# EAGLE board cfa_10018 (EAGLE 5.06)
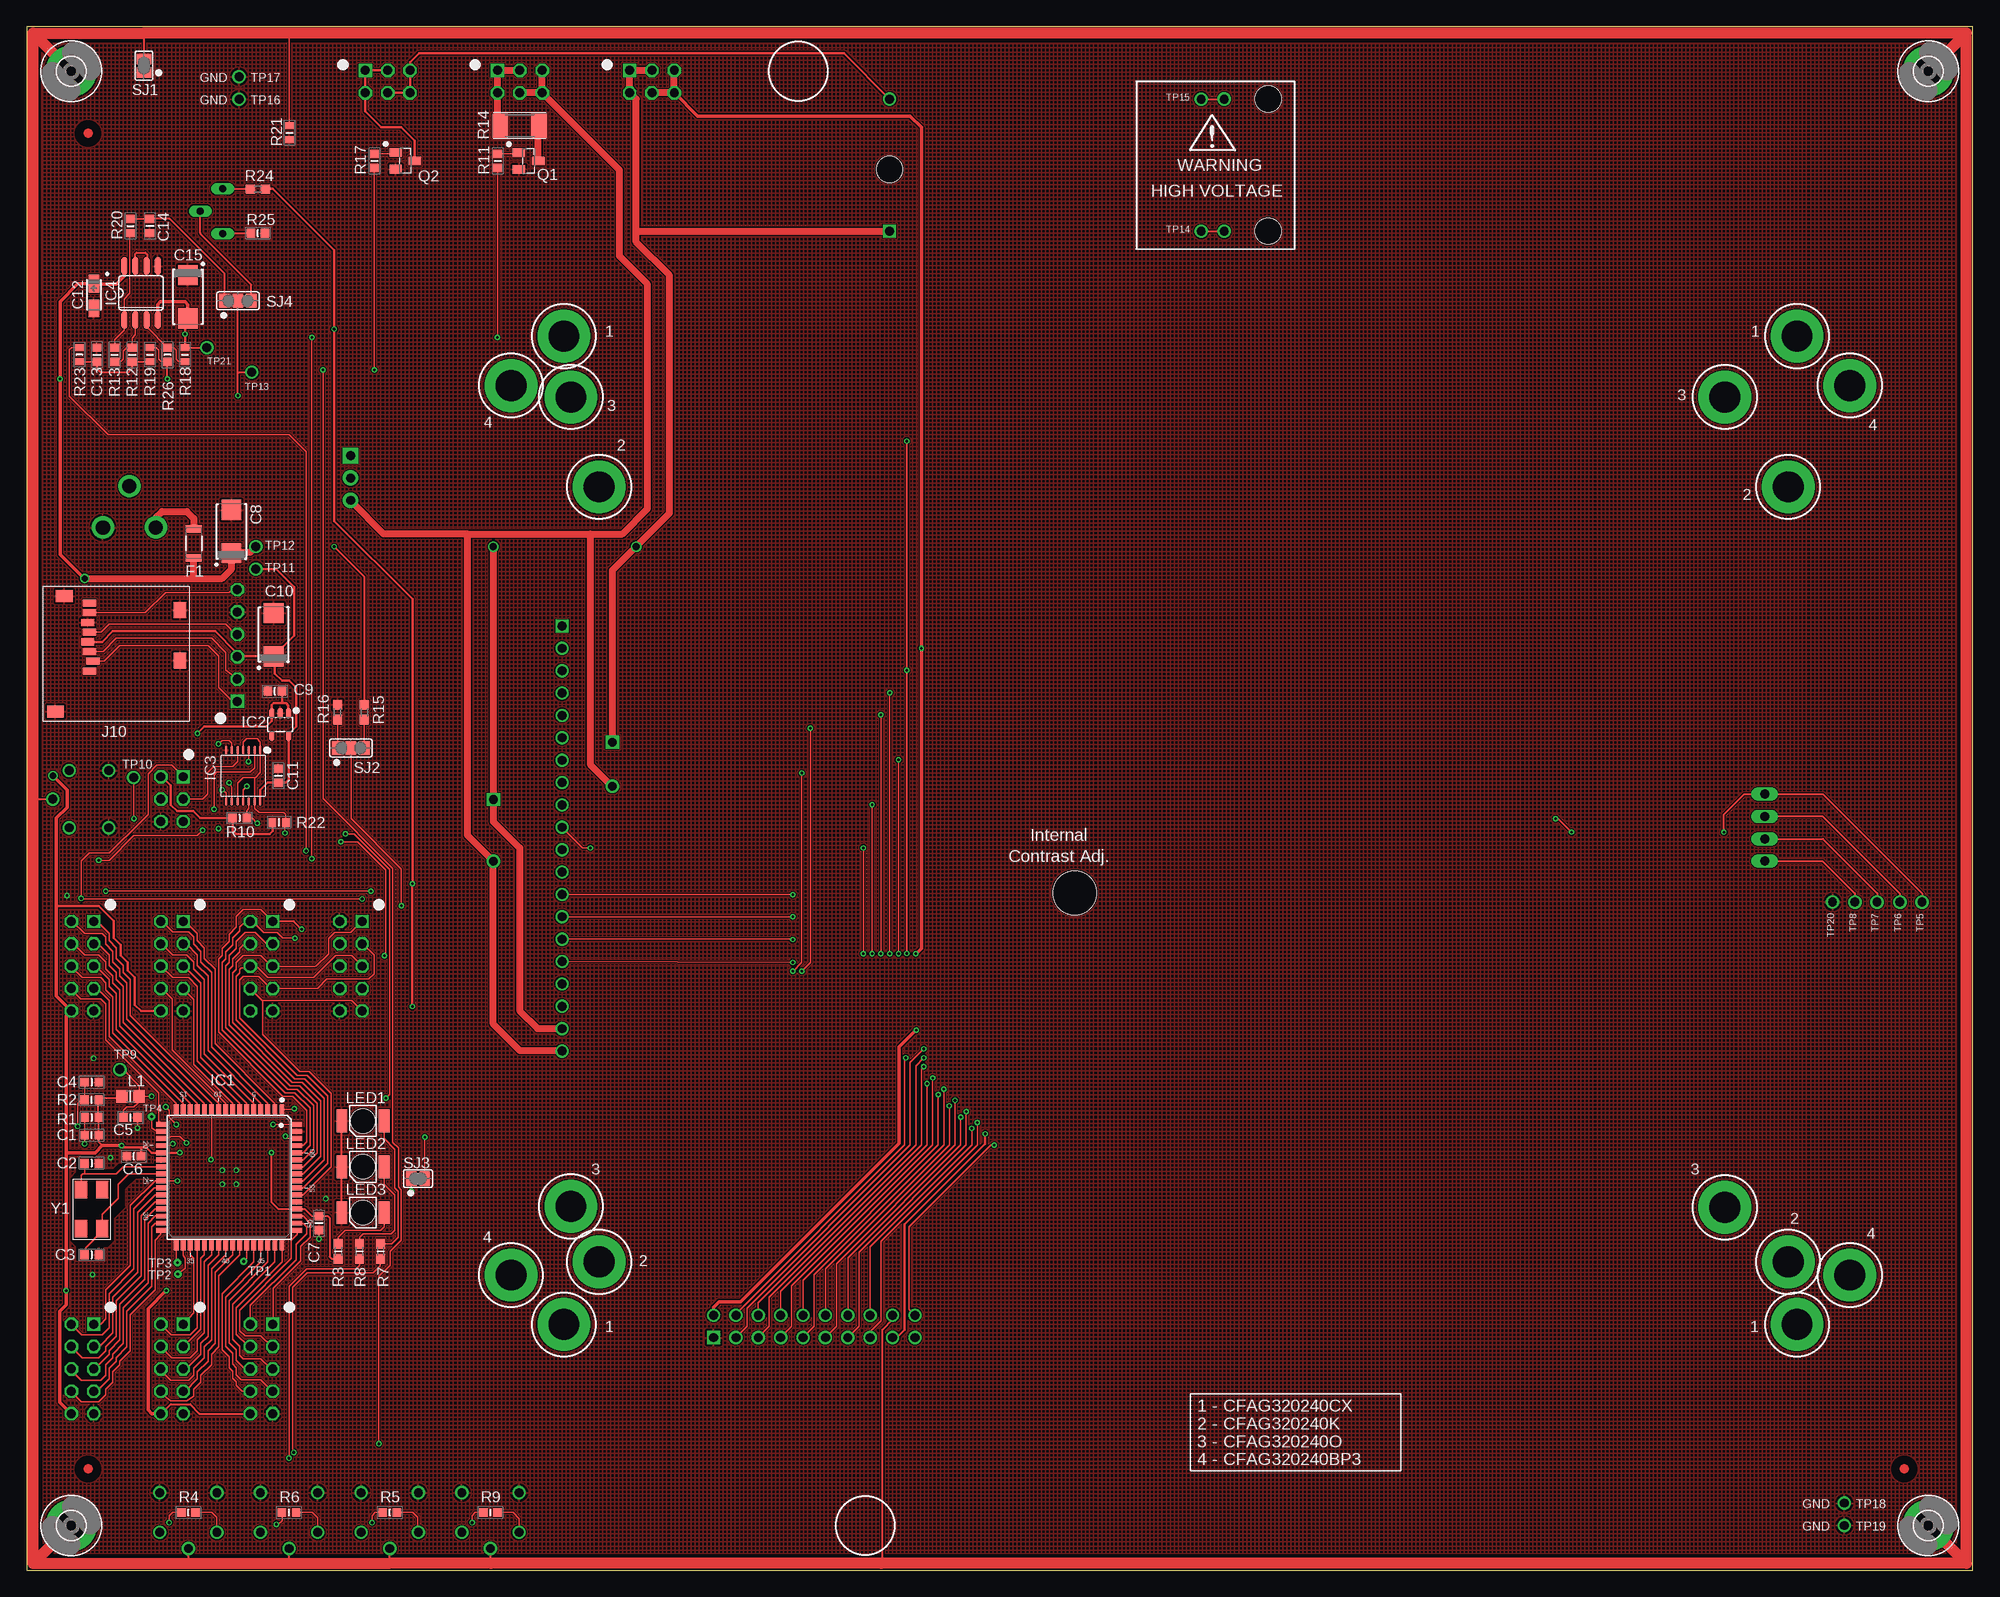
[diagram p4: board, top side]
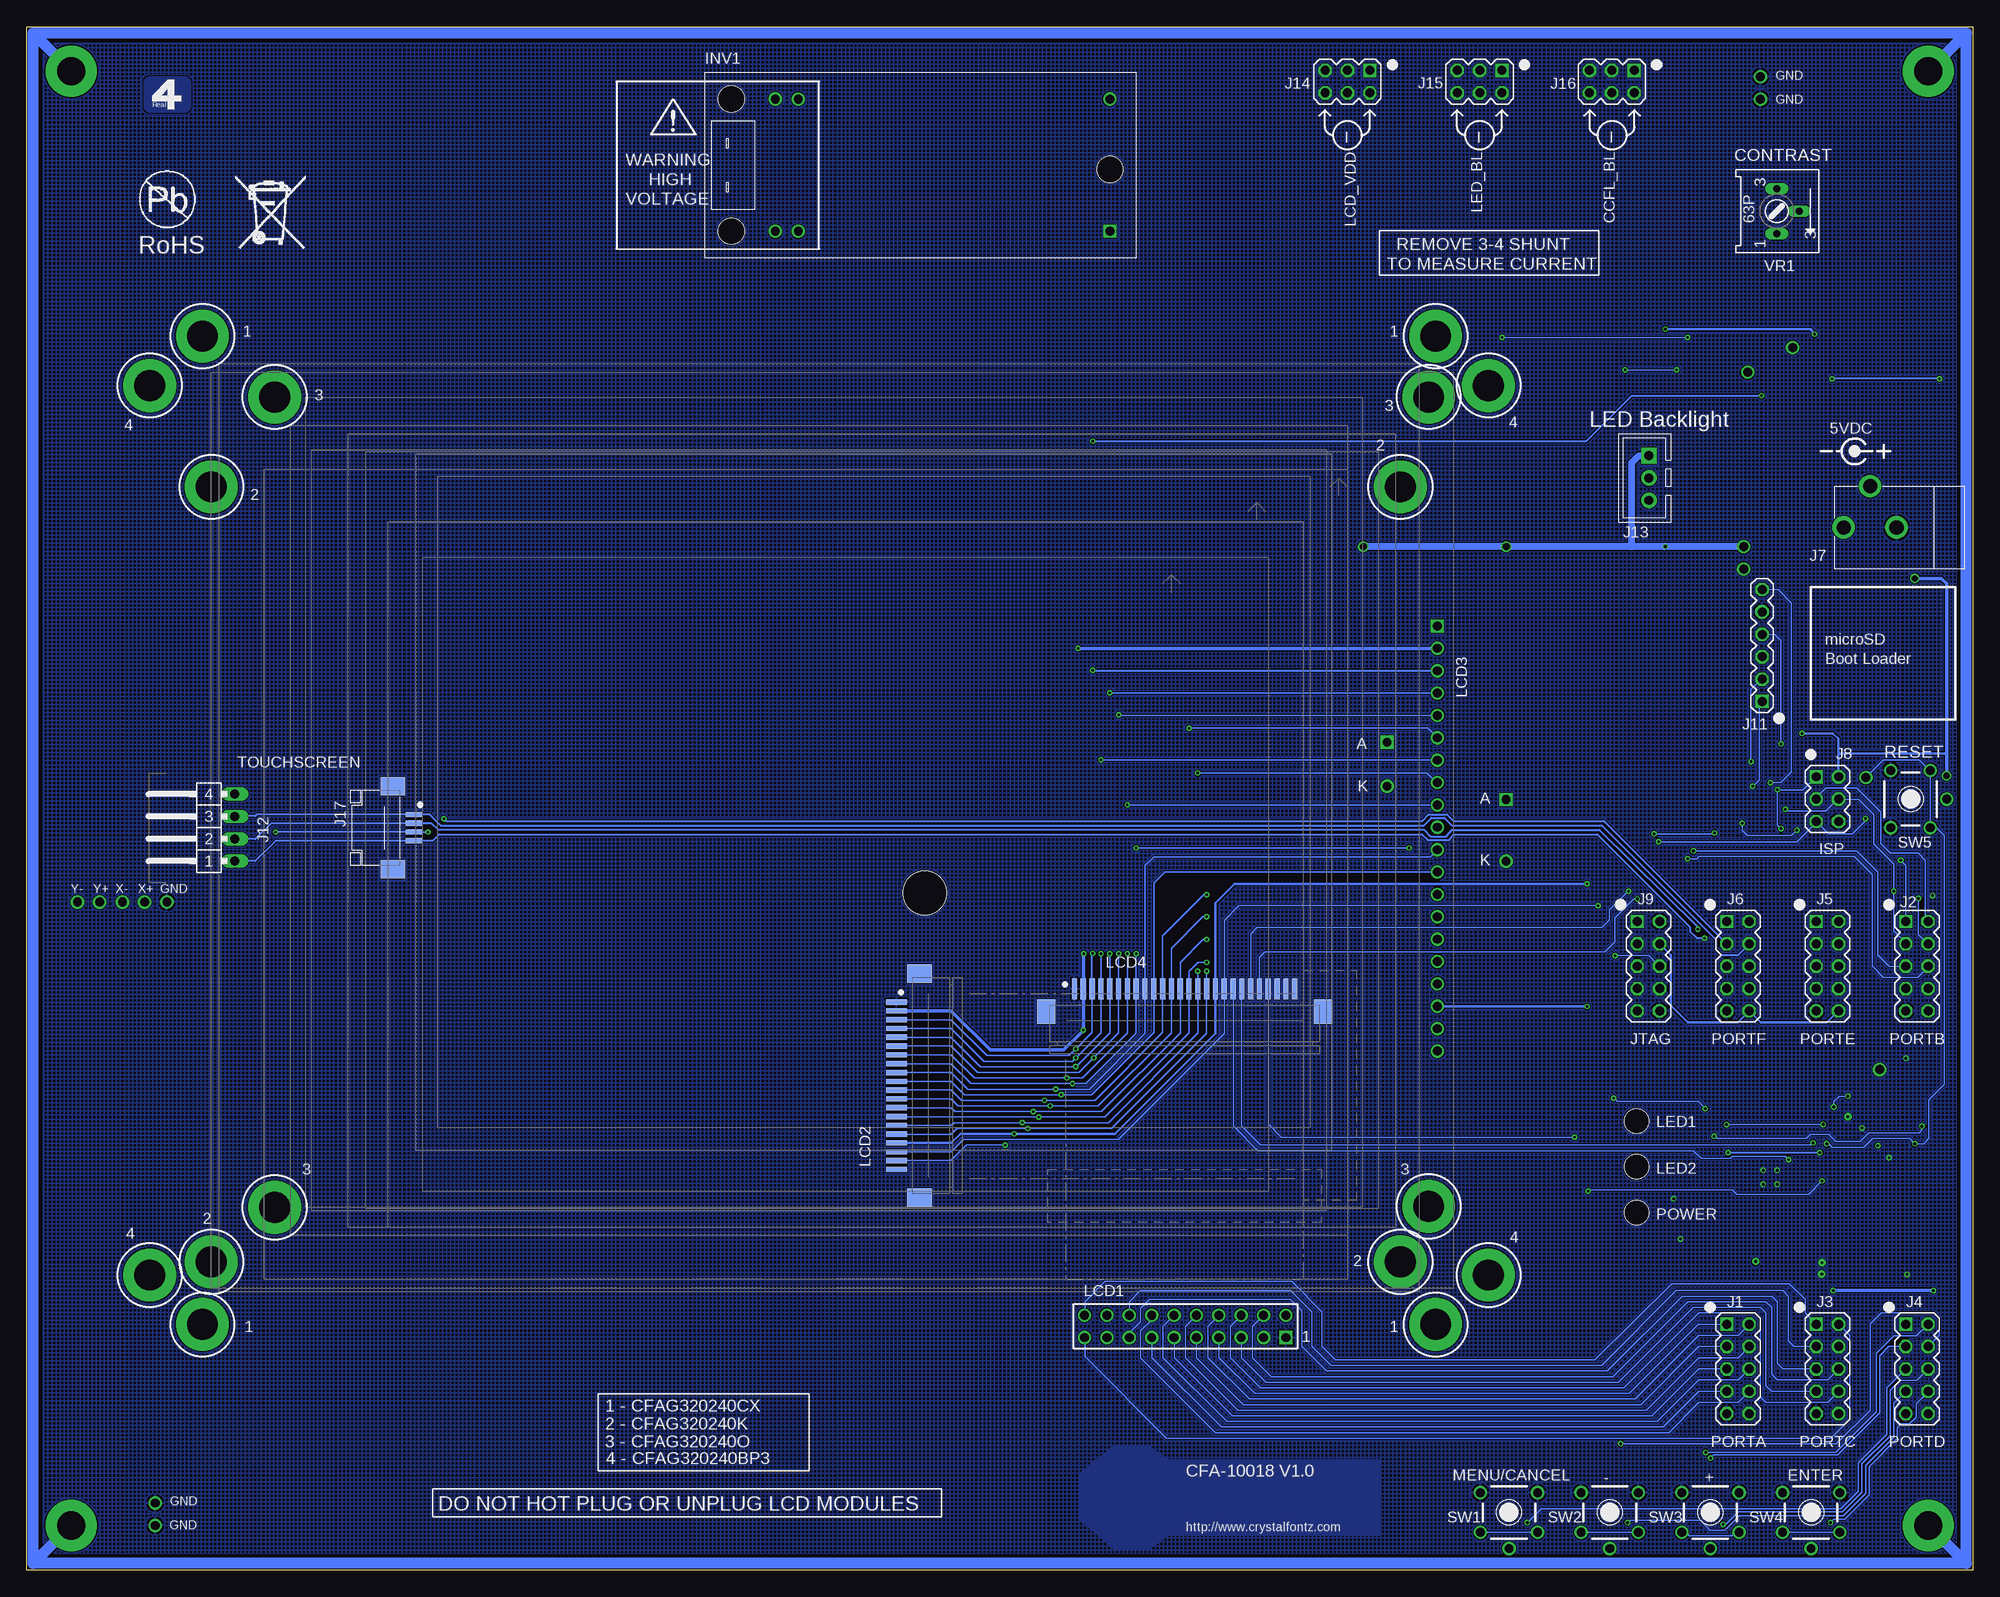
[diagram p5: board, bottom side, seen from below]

Size 220.98 x 175.26 mm. Coordinates in mm from the lower left corner, seen from the top.
Outline: 0,0 220.98,0 220.98,175.26 0,175.26 0,0
Copper layers (1*2+15*16): Top 0.0254mm / dielectric 0.2032mm / Route2 0.0254mm / dielectric 1.4986mm / Route15 0.0254mm / dielectric 0.2032mm / Bottom 0.0254mm
Design rules "crystalfontz-2-layer": minimum track width 5mil, minimum drill 7mil, track to track 5mil, track to pad 5mil, pad to pad 5mil, via to via 5mil, smd to smd 5mil, copper to edge 5mil, drill to drill 10mil, minimum pad ring 10mil, minimum via ring 6mil, stop-mask expansion 0mil, vias tented up to drill 0mil, thermal gap 10mil
tRestrict: area 5.5,10 to 8.5,13; area 5.5,161.6 to 8.5,164.6; area 211.7,10 to 214.7,13; area 5.1,35.2 to 16.2,46.7

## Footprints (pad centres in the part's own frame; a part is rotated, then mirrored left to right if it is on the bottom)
EVQPB = drill 1 round: A -2.25,3.25; A' -2.25,-3.25; B 2.25,3.25; B' 2.25,-3.25; G 4.1,0
CAPC1608X90N = smd 0.9 x 0.95: 1 -0.8,0; 2 0.8,0
CAPC1608X87N = smd 0.95 x 1: 1 -0.8,0; 2 0.8,0
CAPMP6032X250N = smd 2.3 x 2.25: 1 -2.45,0; 2 2.45,0
CT3216 = smd 2 x 1.2: + -1.4,0; - 1.4,0
RESC3216X85N = smd 0.85 x 1.8: 1 -1.65,0; 2 1.65,0
3,2-PAD = drill 3.2 pad 5.842 round: B3,2 0,0
TQFP64-AEB = smd 1.194 x 0.559: 1 -7.7,6; 2 -7.7,5.2; 3 -7.7,4.4; 4 -7.7,3.6; 5 -7.7,2.8; 6 -7.7,2; 7 -7.7,1.2; 8 -7.7,0.4; 9 -7.7,-0.4; 10 -7.7,-1.2; 11 -7.7,-2; 12 -7.7,-2.8; 13 -7.7,-3.6; 14 -7.7,-4.4; 15 -7.7,-5.2; 16 -7.7,-6; 33 7.7,-6; 34 7.7,-5.2; 35 7.7,-4.4; 36 7.7,-3.6; 37 7.7,-2.8; 38 7.7,-2; 39 7.7,-1.2; 40 7.7,-0.4; 41 7.7,0.4; 42 7.7,1.2; 43 7.7,2; 44 7.7,2.8; 45 7.7,3.6; 46 7.7,4.4; 47 7.7,5.2; 48 7.7,6 | smd 0.559 x 1.194: 17 -6,-7.7; 18 -5.2,-7.7; 19 -4.4,-7.7; 20 -3.6,-7.7; 21 -2.8,-7.7; 22 -2,-7.7; 23 -1.2,-7.7; 24 -0.4,-7.7; 25 0.4,-7.7; 26 1.2,-7.7; 27 2,-7.7; 28 2.8,-7.7; 29 3.6,-7.7; 30 4.4,-7.7; 31 5.2,-7.7; 32 6,-7.7; 49 6,7.7; 50 5.2,7.7; 51 4.4,7.7; 52 3.6,7.7; 53 2.8,7.7; 54 2,7.7; 55 1.2,7.7; 56 0.4,7.7; 57 -0.4,7.7; 58 -1.2,7.7; 59 -2,7.7; 60 -2.8,7.7; 61 -3.6,7.7; 62 -4.4,7.7; 63 -5.2,7.7; 64 -6,7.7
SOT23-5L = smd 0.55 x 1.2: 1 -0.95,-1.3; 2 0,-1.3; 3 0.95,-1.3; 4 0.95,1.3; 5 -0.95,1.3
TSSOP14 = smd 0.305 x 0.991: 1 -1.95,-2.918; 2 -1.3,-2.918; 3 -0.65,-2.918; 4 0,-2.918; 5 0.65,-2.918; 6 1.3,-2.918; 7 1.95,-2.918; 8 1.95,2.918; 9 1.3,2.918; 10 0.65,2.918; 11 0,2.918; 12 -0.65,2.918; 13 -1.3,2.918; 14 -1.95,2.918
SO08 = smd 0.66 x 2.032: 1 -1.905,-3.073; 2 -0.635,-3.073; 3 0.635,-3.073; 4 1.905,-3.073; 5 1.905,3.073; 6 0.635,3.073; 7 -0.635,3.073; 8 -1.905,3.073
CFAICCFL1 = drill 1 square: 1 22,-7 | drill 1 round: 2 22,8; 3 -16,-7; 4 -16,8 | hole 3: -21,8; -21,-7; 22,0
MA05-2 = drill 1.016 square: 1 -5.08,-1.27 | drill 1.016 octagon: 2 -5.08,1.27; 3 -2.54,-1.27; 4 -2.54,1.27; 5 0,-1.27; 6 0,1.27; 7 2.54,-1.27; 8 2.54,1.27; 9 5.08,-1.27; 10 5.08,1.27
PJ-102AH = drill 1.6 pad 2.54 round: 1 -3,0; 2 3,0; 3 0,4.7
MA03-2 = drill 1.016 square: 1 -2.54,-1.27 | drill 1.016 octagon: 2 -2.54,1.27; 3 0,-1.27; 4 0,1.27; 5 2.54,-1.27; 6 2.54,1.27
3M_MICROSD = smd 0.8 x 1.5: 1 -6.89,10.3; 2 -5.79,9.9; 3 -4.69,10.3; 4 -3.59,10.5; 5 -2.49,10.3; 6 -1.39,10.5; 7 -0.29,10.3; 8 0.81,10.3 | smd 1.8 x 1.4: GND1 0,0; GND2 -5.7,0 | smd 1.4 x 1.9: GND3 -11.5,14.15; GND4 1.6,13.15
MA06-1 = drill 1.016 square: 1 -6.35,0 | drill 1.016 octagon: 2 -3.81,0; 3 -1.27,0; 4 1.27,0; 5 3.81,0; 6 6.35,0
MA04-1W = drill 1.016 long: 1 -3.79,0; 2 -1.25,0; 3 1.29,0; 4 3.83,0
JST_XHP3 = drill 1 pad 1.778 square: 1 -2.54,0.48 | drill 1 pad 1.778 round: 2 0,0.48; 3 2.54,0.48
52207-0485 = smd 0.6 x 1.9: 1 -1.5,0; 2 -0.5,0; 3 0.5,0; 4 1.5,0 | smd 2.1 x 2.8: P$1 -4.7,-2.4; P$2 4.7,-2.4
R0805 = smd 1.3 x 1.5: 1 -0.95,0; 2 0.95,0
CFAG320240_148_120 = drill 1 square: 1 53,-57.6 | drill 1 round: 2 53,-55.06; 3 50.46,-57.6; 4 50.46,-55.06; 5 47.92,-57.6; 6 47.92,-55.06; 7 45.38,-57.6; 8 45.38,-55.06; 9 42.84,-57.6; 10 42.84,-55.06; 11 40.3,-57.6; 12 40.3,-55.06; 13 37.76,-57.6; 14 37.76,-55.06; 15 35.22,-57.6; 16 35.22,-55.06; 17 32.68,-57.6; 18 32.68,-55.06; 19 30.14,-57.6; 20 30.14,-55.06 | drill 3.5 pad 6 round: P$1 -70,-56.1; P$2 70,-56.1; P$3 70,56.1; P$4 -70,56.1 | hole 5: 12,-7.1
CFAG320240K = smd 2.4 x 0.6: 1 11.8,-14.5; 2 11.8,-15.5; 3 11.8,-16.5; 4 11.8,-17.5; 5 11.8,-18.5; 6 11.8,-19.5; 7 11.8,-20.5; 8 11.8,-21.5; 9 11.8,-22.5; 10 11.8,-23.5; 11 11.8,-24.5; 12 11.8,-25.5; 13 11.8,-26.5; 14 11.8,-27.5; 15 11.8,-28.5; 16 11.8,-29.5; 17 11.8,-30.5; 18 11.8,-31.5; 19 11.8,-32.5; 20 11.8,-33.5 | drill 1 square: A 67.5,15 | drill 1 round: K 67.5,10 | drill 3.5 pad 6 round: P$1 -66,-44; P$2 69,-44; P$3 69,44; P$4 -66,44 | smd 2.8 x 2.1: P$5 14.4,-36.7; P$6 14.4,-11.3
CFAG320240O = drill 1 square: 1 66.5,20 | drill 1 round: 2 66.5,17.46; 3 66.5,14.92; 4 66.5,12.38; 5 66.5,9.84; 6 66.5,7.3; 7 66.5,4.76; 8 66.5,2.22; 9 66.5,-0.32; 10 66.5,-2.86; 11 66.5,-5.4; 12 66.5,-7.94; 13 66.5,-10.48; 14 66.5,-13.02; 15 66.5,-15.56; 16 66.5,-18.1; 17 66.5,-20.64; 18 66.5,-23.18; 19 66.5,-25.72; 20 66.5,-28.26 | drill 3.5 pad 6 round: P$1 -65.5,-46; P$2 65.5,-45.9; P$3 65.5,46; P$4 -65.5,46
CFAG320240BP3 = smd 0.6 x 2.4: 1 29,-18; 2 30,-18; 3 31,-18; 4 32,-18; 5 33,-18; 6 34,-18; 7 35,-18; 8 36,-18; 9 37,-18; 10 38,-18; 11 39,-18; 12 40,-18; 13 41,-18; 14 42,-18; 15 43,-18; 16 44,-18; 17 45,-18; 18 46,-18; 19 47,-18; 20 48,-18; 21 49,-18; 22 50,-18; 23 51,-18; 24 52,-18; 25 53,-18; 26 54,-18 | drill 1 square: A 78,3.5 | drill 1 round: K 78,-3.5 | drill 3.5 pad 6 round: P$1 -76,-50.5; P$2 76,-50.5; P$3 76,50.5; P$4 -76,50.5 | smd 2.1 x 2.8: P$5 25.8,-20.6; P$6 57.2,-20.6
T776_LED_BOTTOM = smd 1.2 x 2.6: A -2.4,0; K 2.4,0 | hole 2.8: 0,0
SOT23 = smd 1 x 1.4: 1 -0.95,-1.1; 2 0.95,-1.1; 3 0,1.1
RESC1608X50N = smd 0.85 x 1: 1 -0.75,0; 2 0.75,0
RESC1608X38N = smd 0.95 x 1: 1 -0.8,0; 2 0.8,0
R0603 = smd 1.1 x 1: 1 -0.85,0; 2 0.85,0
R2010 = smd 1.8 x 2.7: 1 -2.2,0; 2 2.2,0
RESC1608X55N = smd 0.8 x 0.95: 1 -0.8,0; 2 0.8,0
SJ = smd 1.168 x 1.6: 1 -0.762,0; 2 0.762,0
SJ_2 = smd 1.168 x 1.6: 1 -1.524,0; 2 0,0; 3 1.524,0
VIA-3.2MM-HOLE = drill 0.32 round: 1 0,0
VIA-1MM-HOLE = drill 1 round: 1 0,0
S63P = drill 0.813 long: A 2.54,0; E -2.54,0; S 0,2.54
ECX-64 = smd 2 x 1.4: 1 -2.2,-1.2; 2 2.2,-1.2; 3 2.2,1.2; 4 -2.2,1.2

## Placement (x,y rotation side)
+  00202  [EVQPB]  29.81,6.55 270 bottom
-  00202  [EVQPB]  41.24,6.55 270 bottom
C1  00204  [CAPC1608X90N]  7.4,49.4 180 top
C2  00127  [CAPC1608X87N]  7.4,46.2 0 top
C3  00127  [CAPC1608X87N]  7.4,35.8 0 top
C4  00133  [CAPC1608X87N]  7.4,55.4 0 top
C5  00133  [CAPC1608X87N]  11.8,51.4 0 top
C6  00133  [CAPC1608X87N]  12.2,47 180 top
C7  00133  [CAPC1608X87N]  33.2,39.4 270 top
C8  00154  [CAPMP6032X250N]  23.27,117.92 90 top
C9  00133  [CAPC1608X87N]  28.2,99.8 180 top
C10  00154  [CAPMP6032X250N]  28.07,106.22 90 top
C11  00133  [CAPC1608X87N]  28.6,90.2 90 top
C12  00423  [CT3216]  7.66,144.66 270 top
C13  00133  [CAPC1608X87N]  8,138 90 top
C14  00147  [CAPC1608X87N]  14,152.6 270 top
C15  00477  [CAPMP6032X250N]  18.32,144.57 270 top
ENTER  00202  [EVQPB]  18.38,6.55 270 bottom
F1  00199  [RESC3216X85N]  19,116.6 270 top
H1  MOUNT-PAD-ROUND3.2  [3,2-PAD]  215.9,5.08 0 top
H2  MOUNT-PAD-ROUND3.2  [3,2-PAD]  215.9,170.18 0 top
H3  MOUNT-PAD-ROUND3.2  [3,2-PAD]  5.08,170.18 0 top
H4  MOUNT-PAD-ROUND3.2  [3,2-PAD]  5.08,5.08 0 top
IC1  00121  [TQFP64-AEB]  23,44.6 270 top
IC2  00156  [SOT23-5L]  28.8,96 180 top
IC3  00157  [TSSOP14]  24.6,90.2 180 top
IC4  00468  [SO08]  13,145 0 top
INV1  00464  [CFAICCFL1]  119.98,159.02 0 bottom
J1  00144-10-NI  [MA05-2]  26.68,22.85 270 bottom
J2  00144-10-NI  [MA05-2]  6.36,68.57 270 bottom
J3  00144-10-NI  [MA05-2]  16.52,22.85 270 bottom
J4  00144-10-NI  [MA05-2]  6.36,22.85 270 bottom
J5  00144-10-NI  [MA05-2]  16.52,68.57 270 bottom
J6  00144-10-NI  [MA05-2]  26.68,68.57 270 bottom
J7  00142  [PJ-102AH]  11.68,118.38 0 bottom
J8  00144-6-NI  [MA03-2]  16.52,87.54 270 bottom
J9  00144-10-NI  [MA05-2]  36.84,68.57 270 bottom
J10  00155  [3M_MICROSD]  17.44,108.99 90 top
J11  00145-6-NI  [MA06-1]  23.93,104.98 90 bottom
J12  00462  [MA04-1W]  197.33,84.29 90 bottom
J13  00465  [JST_XHP3]  37.27,124 270 bottom
J14  00144-6  [MA03-2]  71,169 180 bottom
J15  00144-6  [MA03-2]  56.01,169 180 bottom
J16  00144-6  [MA03-2]  41.01,169 180 bottom
J17  00441  [52207-0485]  177,84.3 270 bottom
L1  00148  [R0805]  11.8,53.8 0 top
LCD1  00463  [CFAG320240_148_120]  131,84 0 bottom
LCD2  00473  [CFAG320240K]  134,79 0 bottom
LCD3  00480  [CFAG320240O]  127.3,87.2 0 bottom
LCD4  00474  [CFAG320240BP3]  131,84 0 bottom
LED1  00180  [T776_LED_BOTTOM]  38.2,51 180 top
LED2  00180  [T776_LED_BOTTOM]  38.2,45.8 180 top
LED3  00229  [T776_LED_BOTTOM]  38.2,40.6 180 top
MENU/CANCEL  00202  [EVQPB]  52.67,6.55 270 bottom
Q1  00130  [SOT23]  57,159.99 270 top
Q2  00130  [SOT23]  43,160 270 top
R1  00203  [RESC1608X50N]  7.4,51.4 0 top
R2  00134  [RESC1608X38N]  7.4,53.4 180 top
R3  00137  [R0603]  35.4,36.2 270 top
R4  00134  [RESC1608X38N]  18.38,6.55 180 top
R5  00134  [RESC1608X38N]  41.24,6.55 180 top
R6  00134  [RESC1608X38N]  29.81,6.55 180 top
R7  00137  [R0603]  40.2,36.2 270 top
R8  00137  [R0603]  37.8,36.2 270 top
R9  00134  [RESC1608X38N]  52.67,6.55 180 top
R10  00135  [RESC1608X38N]  24.2,85.4 0 top
R11  00134  [RESC1608X38N]  53.5,160 90 top
R12  00143  [RESC1608X38N]  12,138 90 top
R13  00135  [RESC1608X38N]  10,138 90 top
R14  00151  [R2010]  56,164 180 top
R15  00136  [R0603]  38.35,97.42 270 top
R16  00136  [R0603]  35.31,97.42 270 top
R17  00134  [RESC1608X38N]  39.49,160 90 top
R18  00419  [RESC1608X55N]  18,138 90 top
R19  00476  [RESC1608X55N]  14,138 90 top
R20  00134  [RESC1608X38N]  11.8,152.6 90 top
R21  00191  [RESC1608X55N]  29.84,163.19 90 top
R22  00203  [RESC1608X50N]  28.68,84.89 180 top
R23  00475  [RESC1608X55N]  6,138 270 top
R24  00136  [R0603]  26.27,156.79 0 top
R25  00227  [RESC1608X38N]  26.27,151.79 180 top
R26  00227  [RESC1608X38N]  16,138 270 top
SJ1  [SJ]  13.34,170.81 90 top
SJ2  [SJ_2]  36.82,93.36 0 top
SJ3  [SJ]  44.44,44.46 0 top
SJ4  [SJ_2]  24,144.11 0 top
SW5  00202  [EVQPB]  7.09,87.54 0 bottom
TP1  TP-VIA-3.2MM  [VIA-3.2MM-HOLE]  24.66,35.06 0 top
TP2  TP-VIA-3.2MM  [VIA-3.2MM-HOLE]  17.18,33.62 0 top
TP3  TP-VIA-3.2MM  [VIA-3.2MM-HOLE]  17.14,34.92 0 top
TP4  TP-VIA-3.2MM  [VIA-3.2MM-HOLE]  14.2,51.5 0 top
TP5  TP-VIA-1.0MM  [VIA-1MM-HOLE]  215.18,75.85 270 top
TP6  TP-VIA-1.0MM  [VIA-1MM-HOLE]  212.68,75.85 270 top
TP7  TP-VIA-1.0MM  [VIA-1MM-HOLE]  210.08,75.85 270 top
TP8  TP-VIA-1.0MM  [VIA-1MM-HOLE]  207.58,75.85 270 top
TP9  TP-VIA-1.0MM  [VIA-1MM-HOLE]  10.6,56.84 0 top
TP10  TP-VIA-1.0MM  [VIA-1MM-HOLE]  12.16,89.99 0 top
TP11  TP-VIA-1.0MM  [VIA-1MM-HOLE]  26.04,113.67 0 top
TP12  TP-VIA-1.0MM  [VIA-1MM-HOLE]  26.04,116.2 0 top
TP13  TP-VIA-1.0MM  [VIA-1MM-HOLE]  25.57,136.01 0 top
TP14  TP-VIA-1.0MM  [VIA-1MM-HOLE]  133.35,152.02 180 top
TP15  TP-VIA-1.0MM  [VIA-1MM-HOLE]  133.35,167 180 top
TP16  TP-VIA-1.0MM  [VIA-1MM-HOLE]  24.13,167 0 top
TP17  TP-VIA-1.0MM  [VIA-1MM-HOLE]  24.13,169.54 0 top
TP18  TP-VIA-1.0MM  [VIA-1MM-HOLE]  206.38,7.62 0 top
TP19  TP-VIA-1.0MM  [VIA-1MM-HOLE]  206.38,5.08 0 top
TP20  TP-VIA-1.0MM  [VIA-1MM-HOLE]  205.04,75.86 270 top
TP21  TP-VIA-1.0MM  [VIA-1MM-HOLE]  20.47,138.81 0 top
VR1  00470  [S63P]  22.27,154.29 270 bottom
Y1  00126  [ECX-64]  7.4,41 90 top

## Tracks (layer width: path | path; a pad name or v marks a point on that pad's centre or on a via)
!CS_ADS  (via drill 0.3)
  Top 0.152: IC1.19 16.11,49 16.38,49.28 17.4,49.28 v18.16,48.51
  Bottom 0.152: v18.16,48.51 18.41,48.26 80.9,48.26 83.06,50.42 83.06,65.94 LCD4.20
!LCD_CS1  (via drill 0.3)
  Top 0.152: IC1.39 21.8,35.8 20.6,34.6 20.6,26.53 19.8,25.73 19.8,24.53 18.2,22.93 17.85,22.93 J3.5 | LCD1.15 95.78,26.44 95.76,27.05 97.03,28.32 97.03,37.34 107.95,48.26 v107.95,50.8 | v89,95.6 89,69 v88,68
  Bottom 0.152: J3.5 21.59,22.86 22.23,23.5 22.23,30.48 22.86,31.11 33.02,31.11 41.53,22.61 73.41,22.61 76.2,25.4 76.2,29.46 77.47,30.73 93.47,30.73 94.49,29.72 94.49,28.19 95.76,26.92 95.76,26.42 LCD1.15 | LCD2.15 116,50.5 115.7,50.8 v107.95,50.8 98.17,50.8 88,60.97 LCD4.15 v88,68 | LCD3.6 61.9,95.6 v89,95.6
!LCD_RST  (via drill 0.3)
  Top 0.152: IC1.37 20.2,35.8 19.8,35.4 19.8,27.33 18.43,25.96 18.34,25.96 J3.3 | LCD1.16 95.78,36.73 107.31,48.26 v107.31,50.16 | v88,90.5 88,69 v87,68
  Bottom 0.152: J3.3 19.68,25.4 20.32,25.4 20.95,26.04 20.95,31.11 21.59,31.75 33.66,31.75 42.16,23.24 72.9,23.24 75.06,25.4 75.06,29.34 77.47,31.75 94.49,31.75 95.76,30.48 95.76,28.96 LCD1.16 | LCD2.16 116,49.5 115.33,50.16 v107.31,50.16 97.79,50.16 87,60.95 LCD4.16 v87,68 | LCD3.8 60.92,89.42 62,90.5 v88,90.5
!RESET  (via drill 0.3, 0.32)
  Top 0.152: R1.1 6.6,51.4 C1.2 v6.6,48.4 | IC1.20 16.4,48.2 v16.6,48.4 | TP10.1 12.16,85.5 v12.2,85.33 | v35.7,82.7 35.79,82.7 35.69,82.68 37.59,82.68 40.77,79.5 40.77,69.98 v40.63,69.77
  Bottom 0.152: v16.6,48.4 16.4,48.4 16,48 12.4,48 11.4,49 10.2,49 10,49 7.2,49 v6.6,48.4 5.6,48.4 5,49 5,53.4 3.23,55.16 3.23,83.4 4.12,84.29 SW5.B' 4.84,90.76 4.81,90.79 | 4.81,90.79 4.8,90.8 | 4.81,90.79 SW5.B 4.89,90.79 6.1,92 10.2,92 12.2,90 12.19,89.99 TP10.1 | J9.6 35.87,68.82 36.82,69.77 v40.63,69.77 | 17.7,85 | 17.7,85 J8.5 | v35.7,82.7 20,82.7 17.7,85 | v12.2,85.33 12.2,85.1 13.7,83.6 16.4,83.6 J8.5 | J8.5
!SD_SS  (via drill 0.32)
  Top 0.152: J10.2 8.8,103.2 10.6,105 20.6,105 21.8,103.8 21.8,100.2 23.4,98.6 23.8,98.6 23.83,98.63 J11.1 | IC3.11 24.6,88.6 v25,89
  Bottom 0.152: v25,89 24.27,89.73 24.27,98.29 J11.1
!SDEN  (via drill 0.3, 0.32)
  Top 0.152: 30.25,52.3 IC1.1 30.3,52.3 v30.4,52.4 | 26,90 26.55,90.55 IC3.1 26.55,94.05 26.2,94.4 25,94.4 24.6,94 IC3.4 | 26,90 24.6,90 23.95,89.35 IC3.10 | 26,90 25.9,90 IC3.13 25.9,86.5 26.4,86 29.2,86 29.4,85.8 29.4,84.92 R22.1 29.34,84.81 v29.34,83.69 | v40.8,53.6 41.2,54 41.2,79.58 37.21,83.57 36.2,83.57 36.2,83.64 v36.2,83.6
  Bottom 0.152: v30.4,52.4 31.2,53.2 40.4,53.2 v40.8,53.6 | v36.2,83.6 29.43,83.6 v29.34,83.69
!SS  (via drill 0.32)
  Top 0.152: J2.1 8.02,73.65 9.4,72.27 9.4,71.47 10.2,70.67 10.2,69.47 11,68.67 11,67.87 11.8,67.07 11.8,63 21.8,53 IC1.10 | v8.2,80.6 9.4,80.6 12.2,83.4 | 12.2,83.4 | 12.2,83.4 15,83.4 | IC3.12 25.25,86.45 25,86.2 R10.2 25.6,85.4 v26.2,84.8 | v20,84 19.4,83.4 15,83.4 | 15,83.4
  Bottom 0.152: J2.1 7.63,80.03 v8.2,80.6 | v26.2,84.8 26.2,84 25.6,83.4 20.6,83.4 v20,84
+3V3
  Top 0.152: C10.1 28.07,103.53
  Top 0.203: 29.75,94.95 IC2.5 | 24.03,103.77 23.83,103.77 23.8,103.8
  Top 0.254: 28.07,103.53 28.2,103.4
  Top 0.305: J10.4 8.6,105.4 9.8,106.6 21.4,106.6 23.8,104.2 23.8,103.8 23.89,103.71 J11.3 | IC3.14 26.55,88.55 27.4,89.4 C11.1 29.4,89.4 29.75,89.75 IC2.5 | 29.75,94.95 30.6,95.8 30.6,100.2 29.8,101 29,101 28.2,101.8 28.2,103.4 | 24.03,103.77 C10.1 30.4,106.1 30.4,111.6 28.34,113.67 TP11.1
+5V  (via drill 0.3, 0.32, 0.7, 0.8)
  Top 0.152: 13,47.4 C6.1 | 8.2,51.4 R1.2 | 8.15,53.35 R2.1 8.4,53.6 | L1.1 10.8,53.8 10.6,53.6 | 30.6,41 IC1.52 | 15.3,90.2 15.25,90.15 J8.2 | R19.2 14.7,138.8 15,138.5 15,137.5 15.3,137.2 R26.2 | 27.23,95.81 27.21,95.81 27.2,95.8 | 27.81,97.28 IC2.3
  Top 0.203: J3.10 15.27,17.77 | 4.5,47.4 6.2,47.4 | 27.8,97.4 27.85,97.35 IC2.3 | 29.72,97.33 IC2.1 | 28.96,98.42 29,98.47
  Top 0.254: 8.2,51.4 C1.1 8.2,48.6 8.6,48.2 | J1.10 19.63,17.77 18.6,18.85 16.4,18.85 15.27,17.77 | R3.2 34.65,35.35 34.4,35.6 34.4,40 34.2,40.2 C7.1 32.4,40.2 31.6,41 30.6,41 28.6,41 27.8,41.8 v27.8,47.4 | R1.2 8.15,53.35 | 8.4,53.6 10.6,53.6 | R26.2 v16,135.26 v16,135.25 | R15.1 38.35,112.78 v34.92,116.2
  Top 0.305: J5.10 13.01,63.49 12.3,64.2 12.3,67.3 11.5,68.1 11.5,69 10.7,69.8 10.7,71 9.9,71.8 9.9,73.7 8.2,75.4 4.6,75.4 3.4,75.4 | v19.4,95 20.2,95.8 27.2,95.8 | 23.26,115.34 23.2,115.4 C8.1 | C8.1 | 23.5,115.57 23.39,115.47 C8.1 | 13,48 11,48 v10.8,48.2 | 13,48 13.6,48 14.2,47.4 IC1.21 v17.4,47.4 | 13,48 13,47.4 | 15.3,90.2 16.4,89.1 16.4,86.9 17.1,86.2 18.9,86.2 19.7,85.4 R10.1 23.4,84 23.8,83.6 27.6,83.6 27.93,83.92 R22.2 | v69.22,116.2 69.2,116.2 | 68.45,167.72 J14.2 | 69.22,152.02 | 27.23,95.81 27.81,96.39 27.81,97.28 | 27.85,97.35 27.85,98.21 28.07,98.42 28.96,98.42 29.46,98.42 29.72,98.17 29.72,97.33 | 29,98.47 C9.1
  Top 0.406: J3.10 14.23,17.77 13.8,18.2 13.8,29.68 v15.88,31.75 | 4.5,47.4 4.5,62.9 J2.10 3.4,65.18 3.4,75.4 3.4,85.4 4.6,86.6 4.6,88.6 v3,90.2 | 4.5,47.4 6.2,47.4 7.8,47.4 8.6,48.2 v10.8,48.2 | J4.10 3.8,19.06 3.8,29.4 4.5,30.1 v4.5,31.75 4.5,47.4 | IC4.8 11.1,146.9 10.2,146 7.72,146 C12.+ 5.84,146.05 3.81,144.02 v3.81,135.25 3.81,115.32 6.53,112.6 v6.6,112.6
  Top 0.813: 19,112.6 F1.2 | v6.6,112.6 19,112.6 | C8.1 23.27,113.67 22.2,112.6 19,112.6 | TP12.1 25.4,115.57 23.5,115.57 | J14.3 J14.1 J14.2 | v52.99,116.2 52.99,99.06 53,90.47 LCD4.A 53,85 56,82 56,63.5 58,61.5 60.78,61.5 LCD3.19 | 68.45,167.72 69.22,167 69.22,152.02 69.22,150.78 73,147 73,120 69.2,116.2 66.5,113.5 LCD2.A | 69.22,152.02 INV1.1
  Bottom 0.152: v4.5,31.75 4.75,31.75 | 25.39,63.49 J6.10 | 15.3,63.5 15.29,63.49 J5.10 | 15.3,90.13 J8.2 | 15.29,92.7 15.3,92.71
  Bottom 0.254: v17.4,47.4 v27.8,47.4 | v3.81,135.25 v16,135.25 | 35.05,116.2 v34.92,116.2
  Bottom 0.305: 25.39,63.49 24.1,62.2 16.6,62.2 15.3,63.5 | J6.10 26.7,62.2 32.35,62.2 34.29,64.14 34.29,69.83 J9.4 | v19.4,95 15.9,95 15.3,94.4 15.3,92.71 15.3,90.13 | 3,92.7 15.29,92.7
  Bottom 0.406: v6.6,112.6 3.6,112.6 3,112 3,92.7 v3,90.2 | v4.5,31.75 v15.88,31.75
  Bottom 0.813: TP12.1 35.05,116.2 38.73,116.2 | 38.73,116.2 v52.99,116.2 v69.22,116.2 | J13.1 37.92,126.54 38.73,125.73 38.73,116.2
AVCC  (via drill 0.32, 0.35)
  Top 0.152: v17,50.6 16.2,51.4 16.2,52.2 v15.8,52.6 | C5.1 11,52.2 11.4,52.6 12.2,52.6 12.6,53 12.6,53.8 L1.2 12.8,53.8 | 12.8,53.8 v14.2,53.8 | TP9.1 10.96,56.84 12.8,55 12.8,53.8 | v28,50.6 IC1.64
  Bottom 0.152: v14.2,53.8 15.2,53.8 15.8,53.2 15.8,53.18 | 15.8,53.18 v15.8,52.6 | 15.8,53.18 15.88,53.18 | v17,50.6 v28,50.6
FOO  (via drill 0.32)
  Top 0.152: v12.6,50.2 C5.2 | C2.2 | 17.4,109 17.41,108.99 J10.GND1 | 8.26,46.2 8.25,46.2 C2.2 | IC1.22 | IC1.63 | IC1.53
  Top 0.203: v33.2,37.6 C7.2 | LED1.K LED2.K LED3.K 35.8,41.4 35.4,41.8 | 30.6,41.8 | IC1.53 30.6,41.8 | J10.GND3 3.29,97.91
  Top 0.254: 28.13,108.67 28.2,108.6 | C10.2 28.13,108.67 | 28.13,108.67 28.01,108.79 | 17.4,109 17.41,108.99 J10.GND1
  other vias: 23.81,45.4 7.62,58.1 7.5,33.58 22.23,45.4 4.6,76.6 9.53,46.83 22.23,43.81 23.81,43.81 33.97,42.16
  pour Bottom (rank 2, hatched): 1.91,173.35 219.07,173.35 219.07,1.91 1.91,1.91
  pour Top (rank 2, hatched): 1.71,173.35 219.07,173.35 219.07,1.91 1.91,1.91
GND1
  pour Bottom (rank 2): 101.35,5.84 101.35,10.92 97.54,13.97 93.47,13.97 91.44,12.45 67.31,12.45 67.31,4.06 91.44,4.06 93.47,2.54 97.54,2.54
GND2
  pour Bottom: 202.46,168.81 arc-90 203.09,169.45 206.89,169.45 arc-90 207.53,168.81 207.53,166.28 arc-90 206.89,165.64 203.09,165.64 arc-90 202.46,166.28
GNDA
  Top 0.152: 29.84,174.5 R21.2
  Top 0.203: 18.41,0.76 ENTER.G | MENU/CANCEL.G 52.7,2.54 52.7,0.76 | SW5.G 0.72,87.54 0.76,87.5 | 13.34,174.5 SJ1.2 | 29.97,0.76 29.97,0.51 29.81,0.67 +.G | -.G 41.24,0.85 41.15,0.76
  Top 0.254: LCD1.18 98.32,28.47 97.16,27.3 97.16,0.76 97.03,0.76
  Top 0.406: SJ1.2 12.7,171.45
  Top 1.016: 1.27,173.99 0.76,173.99
  Top 1.27: 220.22,174.5 29.84,174.5 13.34,174.5 0.76,174.5 0.76,173.99 0.76,87.5 0.76,0.76 | 220.22,0.76 220.22,174.5 | 0.76,0.76 18.41,0.76 29.97,0.76 41.15,0.76 52.7,0.76 97.03,0.76 220.22,0.76 | H3.B3,2 1.27,173.99 | H2.B3,2 220.22,174.5 | H1.B3,2 220.22,0.76 | H4.B3,2 0.76,0.76
  Bottom 1.27: 0.76,174.5 220.22,174.5 | 220.22,0.76 220.22,174.5 | 0.76,0.76 220.22,0.76 | 0.76,0.76 0.76,174.5 | 0.76,174.5 H3.B3,2 | 220.22,174.5 H2.B3,2 | 220.22,0.76 H1.B3,2 | 0.76,0.76 H4.B3,2
LCD_CCFL  (via drill 0.3, 0.32)
  Top 0.152: IC1.28 | IC1.28 14.6,41.8 13,40.2 13,33.4 10.2,30.6 10.2,27.73 | 10.2,27.73 10.2,27.33 | 10.2,27.73 10.2,26.53 9,25.33 9,24.93 8.2,24.13 6.35,24.13 J4.4 | v40.01,14.35 40.01,33.34 41.27,34.61 41.27,36.2 42.55,37.47 42.55,43.18 42.23,43.5 42.23,47.94 41.59,48.58 41.59,79.69 33.66,87.63 v33.66,136.27 | v39.5,136.27 R17.1
  Bottom 0.152: v40.01,14.35 15.49,14.35 11.68,18.16 11.68,27.94 10.41,29.21 4.45,29.21 3.81,28.57 3.81,26.67 J4.4 | v33.66,136.27 v39.5,136.27
LCD_D0  (via drill 0.3)
  Top 0.152: IC1.51 | IC1.51 | IC1.51 31.4,40.2 32.2,39.4 32.2,37.8 31.15,36.75 31.15,35.13 28,31.98 28,27.98 J1.1 | LCD1.7 85.62,26.44 86.87,27.69 86.87,32.26 102.87,48.26 v102.87,55.88 | v96,70 v96,86.9
  Bottom 0.152: J1.1 31.11,27.93 31.11,27.94 38.99,20.07 81.53,20.07 85.6,24.13 85.6,26.38 LCD1.7 | LCD2.7 116,58.5 113.38,55.88 v102.87,55.88 101.09,55.88 96,60.97 LCD4.7 v96,70 | LCD3.9 95.98,86.88 v96,86.9
LCD_D1  (via drill 0.3)
  Top 0.152: IC1.50 | IC1.50 | IC1.50 31.4,39.4 31.8,39 31.8,38.2 30.6,37 30.6,35.25 25.4,30.05 J1.2 | LCD1.8 85.62,31.64 102.23,48.26 v102.23,55.24 | v95,70 v95,82 | v64,82 63.14,82 LCD3.10
  Bottom 0.152: J1.2 26.67,26.67 31.11,26.67 38.35,19.43 82.17,19.43 86.87,24.13 86.87,27.69 LCD1.8 | LCD2.8 116,57.5 113.75,55.24 v102.23,55.24 100.71,55.24 95,60.96 LCD4.8 v95,70 | v95,82 v64,82
LCD_D2  (via drill 0.3)
  Top 0.152: IC1.49 | J1.3 27.81,25.39 26.6,26.6 24.8,26.6 24.2,27.2 24.2,29.53 30.05,35.38 30.05,37.42 30.73,38.1 30.73,38.57 IC1.49 | LCD1.9 88.16,26.44 89.41,27.69 89.41,33.53 104.14,48.26 v104.14,54.61
  Bottom 0.152: J1.3 31.11,25.39 31.11,25.4 37.72,18.8 82.8,18.8 88.14,24.13 88.14,26.38 LCD1.9 | LCD2.9 116,56.5 114.11,54.61 v104.14,54.61 100.33,54.61 94,60.94 LCD4.9 94,80 93,81 61.6,81 LCD3.11
LCD_D3  (via drill 0.3)
  Top 0.152: 29,35 IC1.48 | 29,35 29,35.8 | 29,35 23.8,29.8 23.8,26.8 25.21,25.39 J1.4 | LCD1.10 88.16,32.91 103.5,48.26 v103.5,53.98
  Bottom 0.152: J1.4 26.67,24.13 31.11,24.13 37.08,18.16 83.44,18.16 89.41,24.13 89.41,27.69 LCD1.10 | LCD2.10 116,55.5 114.47,53.98 v103.5,53.98 100.08,53.98 93,61.05 LCD4.10 93,78 91.74,79.26 LCD3.12
LCD_D4  (via drill 0.3)
  Top 0.152: 28.2,35 IC1.47 | 28.2,35 23.4,30.2 23.4,26.2 24.2,25.4 24.2,24.4 24.6,24 26.6,24 27.75,22.85 27.93,22.85 J1.5 | 28.2,35 28.2,35.4 | LCD1.11 90.7,26.44 91.95,27.69 91.95,34.8 105.41,48.26 v105.41,53.34 | LCD3.13 86.78,76.72 v87,76.7
  Bottom 0.152: J1.5 31.11,22.85 31.11,22.86 36.45,17.53 84.07,17.53 90.68,24.13 90.68,26.38 LCD1.11 | LCD2.11 116,54.5 114.84,53.34 v105.41,53.34 99.69,53.34 92,61.03 LCD4.11 92,72 87.3,76.7 v87,76.7
LCD_D5  (via drill 0.3)
  Top 0.152: 27.4,35 IC1.46 | 27.4,35 27.4,35.8 | 27.4,35 23,30.6 23,25.8 23.8,25 23.8,23.8 24.75,22.85 25.39,22.85 J1.6 | LCD1.12 90.7,34.19 104.78,48.26 v104.78,52.7 | LCD3.14 86.82,74.18 v87,74.2
  Bottom 0.152: J1.6 26.67,21.59 31.11,21.59 35.81,16.89 84.71,16.89 91.95,24.13 91.95,27.69 LCD1.12 | LCD2.12 116,53.5 115.2,52.7 v104.78,52.7 99.31,52.7 91,61.02 LCD4.12 91,70.6 87.4,74.2 v87,74.2
LCD_D6  (via drill 0.3)
  Top 0.152: 26.6,35 IC1.45 | 26.6,35 26.6,35.8 | 26.6,35 22.6,31 22.6,25.4 23.4,24.6 23.4,23.4 23.8,23 23.8,22.2 24.4,21.6 26.6,21.6 27.89,20.31 J1.7 | LCD1.13 93.24,26.44 94.49,27.69 94.49,36.07 106.68,48.26 v106.68,52.07 | LCD3.15 86.86,71.64 v87,71.6
  Bottom 0.152: J1.7 31.11,20.31 31.11,20.32 35.18,16.26 85.34,16.26 93.22,24.13 93.22,26.38 LCD1.13 | LCD2.13 116,52.5 115.57,52.07 v106.68,52.07 98.93,52.07 90,61 LCD4.13 90,69 87.4,71.6 v87,71.6
LCD_D7  (via drill 0.3)
  Top 0.152: IC1.44 25.8,35.8 25.8,35 22.2,31.4 22.2,25 23,24.2 23,23 23.4,22.6 23.4,21.8 23.8,21.4 23.8,21 24.49,20.31 J1.8 | LCD1.14 93.24,35.45 106.05,48.26 v106.05,51.44 | v87,69 LCD3.16
  Bottom 0.152: J1.8 26.67,19.05 31.11,19.05 34.54,15.62 85.98,15.62 94.49,24.13 94.49,27.18 93.22,28.45 93.22,28.96 LCD1.14 | LCD2.14 122.14,51.44 v106.05,51.44 98.55,51.44 89,60.99 LCD4.14 89,68 88,69 v87,69
LCD_D/!I  (via drill 0.3)
  Top 0.152: J3.8 15.2,20.26 15.2,20.13 16.4,19.23 18.2,19.23 19,19.73 19,20.53 19.8,21.33 19.8,22.13 21,23.33 21,24.53 21.8,25.33 21.8,33.4 24.2,35.8 IC1.42 | LCD1.6 83.08,30.38 100.97,48.26 100.97,57.28 v101.85,58.17 | v99,70 v99,92
  Bottom 0.152: J3.8 16.51,19.05 23.5,19.05 24.13,19.68 24.13,28.57 24.77,29.21 31.11,29.21 39.62,20.7 80.9,20.7 84.33,24.13 84.33,27.69 LCD1.6 | LCD2.4 116,61.5 112.28,57.78 102.23,57.78 v101.85,58.17 99,61.02 LCD4.4 v99,70 | LCD3.7 98.96,91.96 v99,92
LCD_DOFF
  Top 0.152: J3.2 16.45,26.73 18.6,26.73 19.4,27.53 IC1.36
  Bottom 0.152: J3.2 13.97,26.67 13.97,17.14 16.13,14.99 91.57,14.99 100.84,24.26 100.84,26.38 LCD1.19
LCD_E  (via drill 0.3)
  Top 0.152: 15.2,22.9 15.2,22.93 | 15.2,22.9 J3.6 | 15.2,22.9 15.2,22.73 16.4,21.53 18.4,21.53 19,22.13 19,22.93 20.2,24.13 20.2,25.33 21,26.13 21,34.2 22.6,35.8 IC1.40 | LCD1.4 80.54,29.11 99.69,48.26 99.69,58.04 v99.82,58.17 | v97,70 v97,97.1
  Bottom 0.152: J3.6 16.51,21.59 22.23,21.59 22.86,22.23 22.86,29.84 23.5,30.48 32.38,30.48 40.89,21.97 79.63,21.97 81.79,24.13 81.79,27.69 LCD1.4 | LCD2.6 116,59.5 113.02,56.52 101.47,56.52 v99.82,58.17 97,60.99 LCD4.6 v97,70 | LCD3.5 96.94,97.04 v97,97.1
LCD_R/!W  (via drill 0.3)
  Top 0.152: J3.7 17.8,20.33 18,20.33 19.4,21.73 19.4,22.53 20.6,23.73 20.6,24.93 21.4,25.73 21.4,33.8 23.4,35.8 IC1.41 | LCD1.5 83.08,26.44 84.33,27.69 84.33,30.99 101.6,48.26 101.6,56.9 v101.85,57.15 | v98,70 v98,99.6
  Bottom 0.152: J3.7 19.68,20.31 | 19.68,20.31 19.68,20.32 | 19.68,20.31 22.86,20.32 23.5,20.95 23.5,29.21 24.13,29.84 31.75,29.84 40.26,21.34 80.26,21.34 83.06,24.13 83.06,26.38 LCD1.5 | LCD2.5 116,60.5 112.65,57.15 v101.85,57.15 98,61 LCD4.5 v98,70 | LCD3.4 97.98,99.58 v98,99.6
LCD_SEL  (via drill 0.3)
  Top 0.152: v42.55,75.44 42.55,79.63 36.83,85.34 36.83,93.35 SJ2.2
  Bottom 0.152: 84.96,65.96 LCD4.18 | 84.96,65.96 84.96,60.96 97.03,48.9 114.61,48.9 116,47.5 LCD2.18 | 84.96,65.96 84.96,73.79 83.31,75.44 v42.55,75.44
LCD_VDD  (via drill 0.3)
  Top 0.254: v101,61.31 100.84,61.18
  Top 0.305: 73.57,167.73 J14.6
  Top 0.406: 73.57,167.73 76.2,165.1 100.33,165.1 101.6,163.83 v101.6,104.67 101.6,70.61 v100.97,69.98 | LCD1.2 78,29.87 78.61,30.48 81.08,30.48 99.06,48.46 99.06,59.4 100.84,61.18
  Top 0.813: J14.4 J14.6 J14.5
  Bottom 0.305: 100.97,66.03 LCD4.2
  Bottom 0.406: LCD4.2 v101,61.31 103.25,59.05 111.56,59.05 116,63.5 LCD2.2 | v100.97,69.98 100.97,66.03 | LCD3.2 v101.59,104.66 v101.6,104.67
LCD_VEE-  (via drill 0.3)
  Top 0.203: TP21.1 R18.2
  Top 0.254: 18,141.8 C15.2
  Top 0.305: R18.2 v18,140.33 18,141.8 | LCD1.17 98.79,26.4 99.69,27.3 99.69,39.24 108.84,48.39 v108.84,49.53 | R24.2 27.17,156.84 27.94,156.84 34.92,149.86 v34.92,140.9 34.92,119.13 43.81,110.24 v43.81,77.93 43.8,78.02 v43.8,64
  Top 0.406: IC4.4 14.9,143.71 15.2,144 18,144 18.3,143.7 18.3,142.14 C15.2
  Bottom 0.152: LCD4.17 85.98,65.98
  Bottom 0.305: v43.81,77.93 83.82,77.93 86,75.75 LCD4.17 86,60.94 97.41,49.53 v108.84,49.53 114.97,49.53 116,48.5 LCD2.17 | v34.92,140.9 18.43,140.9 v18,140.33 | LCD3.18 43.82,64.02 v43.8,64
LCD_VO  (via drill 0.3)
  Top 0.152: LCD1.3 80.54,26.44 81.79,27.69 81.79,29.72 100.33,48.26 100.33,57.66 v101.85,59.18
  Top 0.203: TP13.1 24,136.01 24,135.9
  Top 0.254: v99.95,128.19 v99.95,102.16 v99.95,70.02 | v24,133.35 24,135.9 24,143.98 SJ4.2
  Bottom 0.152: LCD4.3 100,61.04 v101.85,59.18 102.62,58.42 111.92,58.42 116,62.5 LCD2.3
  Bottom 0.254: LCD4.3 100,69.96 v99.95,70.02 | v99.95,128.19 43.9,128.19 38.74,133.35 v24,133.35 | LCD3.3 99.91,102.12 v99.95,102.16
LCD_WAIT  (via drill 0.3)
  Top 0.152: J3.1 19,29.21 19,35.4 18.6,35.8 IC1.35 | v109.86,48.26 109.47,48.26 100.2,38.99 100.2,29.59 100.84,28.96 100.97,29.05 LCD1.20
  Bottom 0.152: J3.1 17.79,27.95 19.05,29.21 19.05,30.73 20.83,32.51 34.16,32.51 42.93,23.88 72.39,23.88 73.91,25.4 73.91,29.34 77.34,32.77 98.55,32.77 100.84,30.48 100.84,28.96 LCD1.20 | v109.86,48.26 114.24,48.26 116,46.5 LCD2.19
LED1  (via drill 0.32)
  Top 0.152: IC1.26 14.5,43.4 12.2,41 12.2,34.2 9.4,31.4 9.4,27.93 | 9.4,27.93 9.4,27.73 | 9.4,27.93 9.4,27.53 8.6,26.73 6.29,26.73 J4.2 | v30.35,13.38 30.2,13.78 30.2,32.1 31.88,33.78 39.37,33.78 40.13,34.54 40.13,35.28 R7.2
  Bottom 0.152: v30.35,13.38 30.33,13.38 30.31,13.4 15.56,13.4 11,17.96 11,24.6 9,26.6 6.42,26.6 J4.2
LED2  (via drill 0.32)
  Top 0.152: IC1.27 | IC1.27 14.6,42.6 12.6,40.6 12.6,33.8 9.8,31 9.8,26.93 8.3,25.43 | 8.3,25.43 | J4.3 8.26,25.39 8.3,25.43 | v29.8,12.71 29.8,32.22 31.78,34.2 37.4,34.2 37.8,34.6 R8.2
  Bottom 0.152: J4.3 9.54,25.39 10.6,24.33 10.6,17.85 15.37,13.08 29.43,13.08 v29.8,12.71
LED_BL
  Top 0.813: J15.6 J15.4 | J15.6 J15.5 | J15.6 67.31,158.97 67.31,149.19 70.5,146 70.5,120.5 67.66,117.66 64.01,117.66 | 50.07,117.66 40.54,117.66 36.9,121.3 J13.3 | 50.07,117.66 64.01,117.66 | 64.01,117.66 64.01,91.49 LCD2.K | 50.07,117.66 50.07,83.43 LCD4.K 53,62 56,59 60.74,59 LCD3.20
MISO  (via drill 0.3, 0.32)
  Top 0.152: J2.4 5.36,71.11 6.6,69.87 8.2,69.87 9,69.07 9,68.27 9.8,67.47 9.8,66.67 10.6,65.87 10.6,61.8 19.4,53 IC1.13 | 13,85 9.4,81.4 7.11,81.4 6.22,80.52 v6.2,76.26 6.2,76.2 v38.1,76.2 | IC3.8 22.65,88.25 v22.2,88.6 | 13,85 | 13,85 13.8,85.8 13.8,90.4 14.8,91.4 16.5,91.4 17.8,90.1 J8.1
  Bottom 0.152: J2.4 5.11,71.11 6.2,72.2 v6.2,76.26 | v21.8,84.2 22.2,84.6 v22.2,88.6 19.3,88.6 17.8,90.1 J8.1 | LCD4.22 81,69.58 80.39,70.19 41.78,70.19 40.64,71.34 40.64,74.04 38.48,76.2 v38.1,76.2
MOSI  (via drill 0.3, 0.32)
  Top 0.152: J2.3 8.16,71.11 9.4,69.87 9.4,68.67 10.2,67.87 10.2,67.07 11,66.27 11,62.2 20.2,53 IC1.12 | IC3.2 25.9,91.1 25.4,90.6 21.6,90.6 21.3,90.3 v21.3,86.4 | v9,77.09 v39.12,77.09
  Bottom 0.152: J2.3 7.63,71.17 7.6,71.2 9,72.6 v9,77.09 9,80.2 11.27,82.47 11.27,85.82 12.95,87.5 15.21,87.5 J8.4 | 15.2,87.5 J8.4 | J8.4 15.36,87.54 16.7,86.2 21.1,86.2 v21.3,86.4 | LCD4.21 82,72.23 81.28,72.95 42.16,72.95 41.27,73.84 41.27,74.93 v39.12,77.09
N$1
  Top 0.152: IC1.23 11,45.8 10.2,45 6.6,45 | 6.6,45 6.4,45 6.2,44.8 Y1.3 | 6.6,45 C2.1
N$2
  Top 0.152: 21.6,4.4 21.63,4.37 ENTER.B' | 21.6,4.4 21.5,4.3 | 21.6,4.4 21.6,6 21,6.6 19.2,6.6 19.18,6.58 R4.1
  Bottom 0.152: 21.59,4.3 ENTER.B' | ENTER.B 21.59,4.3 | 21.59,4.3 21.59,4.29
N$3
  Top 0.152: IC1.24 11.6,45 10.4,43.8 10.4,42.2 8.6,40.4 Y1.1 8.6,38.5 6.7,36.6 6.7,35.9 C3.1
N$4
  Top 0.152: 44.43,4.4 44.49,4.34 -.B' | 44.43,4.4 44.33,4.3 | 44.43,4.4 44.43,6 43.83,6.6 42.03,6.6 42.04,6.59 R5.1
  Bottom 0.152: -.B -.B'
N$5  (via drill 0.3)
  Top 0.152: SJ3.2 45.2,48.89 v45.21,49.15
  Bottom 0.152: v45.21,49.15 78.49,49.15 80.01,50.67 LCD4.23
N$6
  Top 0.152: 33.08,4.3 +.B' 33.06,5.93 32.44,6.55 30.73,6.55 30.72,6.57 30.7,6.55 R6.1
  Bottom 0.152: +.B 27,4.3 27.4,3.9 32.2,3.9 32.6,4.3 +.B'
N$7
  Top 0.152: R7.1 41.45,37.05 42.2,37.8 42.2,43 41.8,43.4 41.8,47.8 40.6,49 LED1.A
N$8
  Top 0.152: 55.94,4.3 MENU/CANCEL.B' 55.92,5.85 55.22,6.55 53.54,6.55 53.53,6.55 R9.1
  Bottom 0.152: 55.88,4.3 MENU/CANCEL.B' | MENU/CANCEL.B 55.88,4.3 | 55.88,4.3 55.88,4.29
N$9  (via drill 0.32)
  Top 0.152: v29.39,49.25 29.46,49.15 29.61,49 IC1.62 | v5.8,50.4 5.8,53 6.2,53.4 R2.2 C4.1
  Bottom 0.152: v5.8,50.4 5.8,49.98 6.13,49.65 9.6,49.65 9.8,49.65 11.8,49.65 11.81,49.66 12.8,48.67 12.8,48.65 15.6,48.65 16.4,49.45 18.49,49.45 18.92,49.02 29.11,49.02 v29.39,49.25
N$10
  Top 0.152: R8.1 37.8,37.8 38.2,38.2 41.4,38.2 41.8,38.6 41.8,42.6 40.6,43.8 LED2.A
N$11
  Top 0.152: TP1.1 25,35.4 IC1.43
N$12
  Top 0.203: TP14.1 INV1.3
N$13
  Top 0.152: IC1.34 17.8,35.74 18.02,35.42 18.02,34.26 TP2.1
N$14
  Top 0.61: F1.1 19,118.2
  Top 0.813: J7.1 14.68,119.48 15.4,120.2 18.2,120.2 19,119.4 F1.1
N$15
  Top 0.152: IC1.33 17,35.07 TP3.1
N$16
  Top 0.203: TP15.1 135.98,167 INV1.4
N$17
  Top 0.152: R3.1 35.4,37.8 36.2,38.6 40.2,38.6 40.6,39 LED3.A
N$18
  Top 0.152: IC1.18 14.8,49.8 14.2,50.2 TP4.1
N$19
  Top 0.152: IC4.2 12.37,140.26 12,139.9 R12.2 11.4,138.8 11,138.4 11,137.5 10.7,137.2 R13.1
N$20
  Top 0.152: R13.2 10,139.7 11.1,140.79 IC4.1 11.1,144.32 11.73,144.96 11.73,151.69 11.8,151.75 R20.1
N$22
  Top 0.203: C14.1 R20.2
  Top 0.254: SJ4.1 22.48,147.19 16.26,153.42 14.02,153.42 C14.1
N$25
  Top 0.305: R14.2 53.47,164.33
  Top 0.813: J15.3 J15.1 J15.2 53.47,164.33
N$27
  Top 0.152: R18.1 17.3,137.2 17,137.5 17,138.5 16.7,138.8 R26.1 13.63,141.16 IC4.3
N$30
  Top 0.305: 58.1,163.9 R14.1
  Top 0.813: Q1.3 58.1,163.9
N$31
  Top 0.152: R11.2 55.76,160.8 Q1.1
N$33
  Top 0.152: R15.2 SJ2.3
N$34
  Top 0.152: R16.2 SJ2.1
N$35
  Top 0.203: R19.1 R12.1 12,136.4 11.6,136 8.4,136 8,136.4 C13.1 R23.2
N$36
  Top 0.203: IC4.7 12.37,149.47 12.5,149.6 13.5,149.6 13.7,149.4 13.7,148.14 IC4.6
N$37
  Top 0.305: J16.3 J16.1 J16.2 38.47,165.62 40.26,163.83 42.55,163.83 44.07,162.31 44.07,160.03 Q2.3
N$38
  Top 0.305: J16.4 J16.6 J16.5 43.55,171.19 44.57,172.21 92.79,172.21 INV1.2
N$39
  Top 0.254: VR1.S 19.73,151.81 19.77,151.68 25.53,145.92 25.53,145.13 SJ4.3
N$40
  Top 0.152: R17.2 41.76,160.81 Q2.1
N$41
  Top 0.254: R25.2 22.31,151.79 VR1.A
N$42
  Top 0.254: VR1.E 25.38,156.84 R24.1
PB6
  Top 0.152: J2.7 8.04,66.03 9.4,64.67 9.4,60.6 17,53 IC1.16
PB7
  Top 0.152: IC1.17 | IC1.17 15.4,50.6 15,51 15,54.2 9,60.2 9,64.27 8.4,64.87 6.13,64.87 5.09,65.91 J2.8
PC3
  Top 0.152: J3.4 16.51,24.13 18.6,24.13 19.4,24.93 19.4,26.13 20.2,26.93 20.2,35 21,35.8 IC1.38
PD0  (via drill 0.3)
  Top 0.152: IC1.25 | IC1.25 14.6,44.2 11.8,41.4 11.8,34.6 9,31.8 9,28.53 8.4,27.93 J4.1 | IC1.25 v17.14,44.2 | v43.69,43.05 SJ3.1
  Bottom 0.152: v17.14,44.2 18.67,42.67 26.8,42.67 27.3,43.18 43.56,43.18 v43.69,43.05
PE0
  Top 0.152: J5.1 18.02,73.65 19.4,72.27 19.4,71.47 20.2,70.67 20.2,69.47 21.4,68.27 21.4,59.8 28.2,53 IC1.2
PE1
  Top 0.152: J5.2 15.42,73.65 16.6,72.47 18.4,72.47 19,71.87 19,71.07 19.8,70.27 19.8,69.07 21,67.87 21,59.4 27.4,53 IC1.3
PE2
  Top 0.152: J5.3 18.16,71.11 19.4,69.87 19.4,68.67 20.6,67.47 20.6,59 26.6,53 IC1.4
PE3
  Top 0.152: J5.4 15.36,71.11 16.6,69.87 18.2,69.87 19,69.07 19,68.27 20.2,67.07 20.2,58.6 25.8,53 IC1.5
PE4
  Top 0.152: J5.5 17.9,68.57 19.8,66.67 19.8,58.2 25,53 IC1.6
PE5
  Top 0.152: J5.6 15.3,68.57 16.6,67.27 18.4,67.27 19.4,66.27 19.4,57.8 24.2,53 IC1.7
PE6
  Top 0.152: IC1.8 23.4,53 19,57.4 19,64.8 17.79,66.01 J5.7
PE7
  Top 0.152: IC1.9 22.6,53 16.55,59.05 16.55,64.85 15.4,66 15.28,66 J5.8
PWM1  (via drill 0.3, 0.32)
  Top 0.152: 17.8,52.2 IC1.15 17.8,53 9.8,61 9.8,65.07 9,65.87 9,66.67 8.4,67.27 6.33,67.27 5.09,68.51 J2.6 | v32.38,80.77 v32.38,139.96 | v53.47,139.95 53.47,159.17 R11.1
  Bottom 0.152: v32.38,80.77 31.37,80.77 31.11,81.03 13.46,81.03 11.43,78.99 11.43,68.58 10.16,67.31 6.29,67.31 5.09,68.51 J2.6 | v32.38,139.96 53.37,139.96 v53.47,139.95
PWM2  (via drill 0.32)
  Top 0.152: J2.5 7.9,68.57 9.4,67.07 9.4,66.27 10.2,65.47 10.2,61.4 18.6,53 IC1.14 | v31.75,81.66 31.75,127 29.84,128.91 9.27,128.91 4.88,133.3 4.88,138.56 5.13,138.81 5.99,138.81 R23.1
  Bottom 0.152: J2.5 9.52,68.57 10.79,69.85 10.79,79.25 13.21,81.66 v31.75,81.66
SCK  (via drill 0.3)
  Top 0.152: J2.2 5.22,73.65 6.6,72.27 8.6,72.27 9,71.87 9,71.07 9.8,70.27 9.8,69.07 10.6,68.27 10.6,67.47 11.4,66.67 11.4,62.6 21,53 IC1.11 21,46.65 v20.95,46.61 | IC3.5 23.95,91.8 23.4,91.25 21.4,91.25 21.27,91.25 20.57,90.55 20.57,88.1 20.01,87.54 J8.3
  Bottom 0.152: 11.94,87.54 10.49,86.09 10.49,82.49 9.4,81.4 6.2,81.4 5.4,80.6 5.4,74.2 5.09,73.71 J2.2 | 11.94,87.54 | 11.94,87.54 13.2,88.8 16.7,88.8 17.9,87.6 17.84,87.54 J8.3 | v20.95,46.61 21.34,46.99 27.3,46.99 27.56,46.74 30.86,46.74 31.75,47.62 81.15,47.62 83.95,50.42 83.95,65.95 LCD4.19
SD_MISO  (via drill 0.32)
  Top 0.152: J10.7 13.5,108.7 15.8,111 23,111 23.33,111.33 J11.6 | IC3.9 23.3,88.9 v23,89.4
  Bottom 0.152: v23,89.4 21.8,89.4 20.6,90.6 20.6,109.8 22.13,111.33 J11.6
SD_MOSI  (via drill 0.32)
  Top 0.152: J10.3 8.7,104.3 10.2,105.8 21,105.8 22.6,104.2 22.6,102.2 23.97,101.17 | 23.97,101.17 24,101.2 | IC3.3 25.25,91.85 v25.2,91.8 | 23.97,101.17 J11.2
  Bottom 0.152: J11.2 23.97,101.17 24,101.2 25.2,100 v25.2,91.8
SD_SCK  (via drill 0.32)
  Top 0.152: J10.5 8.5,106.5 9.4,107.4 22.6,107.4 23.75,106.25 J11.4 | v21.8,93.8 22.2,94.2 23,94.2 23.3,93.9 IC3.6
  Bottom 0.152: v21.8,93.8 21.8,105.55 22.5,106.25 J11.4
SW1  (via drill 0.32)
  Top 0.152: IC1.29 | IC1.29 14.6,41 13.4,39.8 13.4,33 10.6,30.2 10.6,26.13 9.4,24.93 9.4,24.53 7.8,22.93 7.6,22.93 7.6,22.88 J4.5 | R9.2 50.95,6.55 50.6,6.2 v50.6,5.4
  Bottom 0.152: v50.6,5.4 49.02,6.99 14.99,6.99 13,8.97 13,12.2 9.8,15.4 9.8,20.68 J4.5
SW2  (via drill 0.32)
  Top 0.152: IC1.30 | IC1.30 14.6,40.2 13.8,39.4 13.8,32.6 11,29.8 11,25.73 9.8,24.53 9.8,24.13 9,23.33 9,22.13 8.4,21.53 6.2,21.53 5,22.73 5,22.76 J4.6 | v28.37,5.2 28.6,5.2 29,5.6 29,6.4 29.01,6.41 R6.2
  Bottom 0.152: J4.6 5.08,22.86 | J4.6 | J4.6 6.4,21.54 8.26,21.54 9.4,20.4 9.4,15.25 12.6,12.05 12.6,9.11 12.61,8.85 14.86,6.6 26.67,6.6 28.07,5.21 v28.37,5.2
SW3  (via drill 0.32)
  Top 0.152: IC1.31 | IC1.31 14.6,39.4 14.2,39 14.2,32.2 11.4,29.4 11.4,25.33 10.2,24.13 10.2,23.73 9.4,22.93 9.4,21.73 8,20.33 7.61,20.33 | 7.61,20.33 7.6,20.33 | J4.7 7.61,20.33 | R5.2 39.58,6.55 39.23,6.2 v39.23,5.4
  Bottom 0.152: J4.7 9,18.94 9,15.11 12.2,11.91 12.2,8.71 14.71,6.2 26.53,6.2 28.2,4.53 29.88,4.53 30.88,5.65 38.92,5.65 39.12,5.46 v39.23,5.4
SW4  (via drill 0.32)
  Top 0.152: 14.6,31.8 14.6,37.42 14.6,37.46 15.24,38.1 15.24,38.54 IC1.32 | J4.8 5.07,20.33 5,20.33 6.2,19.13 8.2,19.13 9,19.93 9,20.53 9.8,21.33 9.8,22.53 10.6,23.33 10.6,23.73 11.8,24.93 11.8,29 14.6,31.8 | 14.6,31.8 | R4.2 17.53,6.6 16.6,6.6 16.2,6.2 v16.2,5.4
  Bottom 0.152: v16.2,5.4 15.8,5.8 14.56,5.8 11.8,8.56 11.8,11.76 8.6,14.96 8.6,16.18 8.18,16.6 7.21,16.6 6.45,17.36 6.46,18.87 5.01,20.31 | 5.01,20.31 4.99,20.33 | 5.01,20.31 J4.8
TCK
  Top 0.152: IC1.57 31.4,45 33.4,47 33.4,53.29 31.29,55.4 30.18,55.4 23.4,62.18 23.4,67.8 23.8,68.2 23.8,69 24.6,69.8 26.6,69.8 27.83,68.57 J6.5 32.77,68.57 32.89,68.58 34.3,69.99 34.3,71.7 35,72.4 36.8,72.4 38.1,73.7 38.11,73.69 J9.1
TDI
  Top 0.152: IC1.54 31.4,42.6 34.6,45.8 34.6,54.11 32.11,56.6 31,56.6 26.8,60.8 26.8,64.64 26.77,64.67 | J9.9 36.93,64.67 26.77,64.67 | 26.77,64.67 J6.8
TDO
  Top 0.152: IC1.55 31.4,43.4 34.2,46.2 34.2,53.84 31.84,56.2 30.73,56.2 24.2,62.73 24.2,67 24.6,67.4 26.35,67.4 27.7,66.05 J6.7 33.03,66.03 34.1,67.1 38.85,67.1 39.45,67.7 39.45,69.85 38.19,71.11 J9.3
TMS
  Top 0.152: IC1.56 31.4,44.2 33.8,46.6 33.8,53.56 31.57,55.8 30.45,55.8 23.8,62.45 23.8,67.4 24.2,67.8 24.2,68.2 24.4,68.4 25.2,68.4 25.4,68.6 25.41,68.59 J6.6 26.13,68.57 27.4,67.3 32.6,67.3 35.1,69.8 36.9,69.8 38.11,68.59 J9.5
TS_X+  (via drill 0.3)
  Top 0.152: IC1.60 31.4,47.4 32.2,48.2 32.2,52.47 30.47,54.2 29.36,54.2 22.2,61.36 22.2,69 22.6,69.4 22.6,70.2 23.4,71 23.4,71.8 24.2,72.6 24.2,73 24.8,73.6 25.4,73.6 25.41,73.61 J6.2 25.65,73.66 26.92,72.39 28.45,72.39 29.08,71.75 v30.48,71.75
  Top 0.203: TP8.1 207.58,76.33 207.58,76.83 203.9,80.52 197.33,80.52 J12.1
  Bottom 0.203: v30.48,71.75 31.37,71.75 32.13,72.52 32.13,73.03 42.65,83.55 58.95,83.55 59.5,82.9 61.9,82.9 62.55,83.55 174.15,83.55 174.9,82.8 J17.4 192.7,82.8 195,80.5 J12.1
TS_X-  (via drill 0.3)
  Top 0.152: IC1.61 31.4,48.2 31.8,48.6 31.8,52.2 30.2,53.8 29.09,53.8 21.8,61.09 21.8,69.4 22.2,69.8 22.2,70.6 23,71.4 23,72.2 23.8,73 23.8,74.2 24.6,75 26.6,75 J6.1
  Top 0.203: v31.24,72.77 30.35,73.66 J6.1 | TP7.1 210.12,76.83 203.94,83.02 197.33,83.02 J12.2
  Bottom 0.152: J6.1
  Bottom 0.203: v31.24,72.77 31.24,73.03 42.4,84.06 59.14,84.06 59.8,83.3 61.6,83.3 62.37,84.07 174.27,84.07 175,84.8 J17.2 193.2,84.8 195,83 197.29,83 J12.2
TS_Y+
  Top 0.152: IC1.58 31.4,45.8 33,47.4 33,53.02 31.02,55 29.91,55 23,61.91 23,68.2 23.4,68.6 23.4,69.4 24.2,70.2 24.2,70.6 24.6,71 25.4,71 25.41,71.01 J6.4
  Top 0.203: TP6.1 212.66,76.83 203.87,85.62 197.33,85.62 J12.3
  Bottom 0.203: J6.4 26.67,69.85 28.57,69.85 29.21,70.48 29.21,71.63 42.15,84.56 59.16,84.56 60,85.4 61.5,85.4 62.34,84.56 173.96,84.56 175.2,85.8 J17.1 194.8,85.8 195,85.6 197.31,85.6 J12.3
TS_Y-  (via drill 0.3)
  Top 0.152: IC1.59 31.4,46.6 32.6,47.8 32.6,52.75 30.75,54.6 29.64,54.6 22.6,61.63 22.6,68.6 23,69 23,69.8 23.8,70.6 23.8,71.4 24.8,72.4 25.96,72.4 27.25,71.11 J6.3
  Top 0.203: TP5.1 215.2,76.83 203.91,88.12 J12.4 197.31,88.1 195,88.1 192.7,85.8 v192.7,83.8 | v173.6,85.3 173.9,85.3 v175.4,83.8
  Bottom 0.203: J6.3 28.45,71.61 28.45,71.63 41.89,85.07 58.97,85.07 59.7,85.8 61.8,85.8 62.53,85.07 173.37,85.07 v173.6,85.3 | v175.4,83.8 J17.3 v192.7,83.8
(copper drawn outside any net)
  shapes: Top circle x3

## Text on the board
tPlace: GND | GND | WARNING | HIGH VOLTAGE | 1 | 1 | 3 | 3 | 4 | 4 | 2 | 2 | Internal | Contrast Adj. | 15 | 10 | 5 | 20 | 60 | 25 | 3 | 3 | 55 | 30 | 50 | 2 | 4 | 4 | 35 | 40 | 45 | 2 | 1 | 1 | 1 - CFAG320240CX | 2 - CFAG320240K | 3 - CFAG320240O | 4 - CFAG320240BP3 | GND | GND
bPlace: GND | GND | l | a | e | R | I | I | I | CCFL_BL | LED_BL | LCD_VDD | CONTRAST | WARNING | HIGH | VOLTAGE | REMOVE 3-4 SHUNT | RoHS | TO MEASURE CURRENT | 1 | 1 | 3 | LED Backlight | 3 | 4 | 5VDC | 4 | 2 | 2 | microSD | Boot Loader | RESET | TOUCHSCREEN | ISP | GND | X+ | X- | Y+ | Y- | PORTB | PORTE | PORTF | JTAG | LED1 | LED2 | 3 | 3 | POWER | 2 | 4 | 4 | 2 | 1 | 1 | 1 - CFAG320240CX | 2 - CFAG320240K | PORTD | PORTC | PORTA | 3 - CFAG320240O | 4 - CFAG320240BP3 | CFA-10018 V1.0 | DO NOT HOT PLUG OR UNPLUG LCD MODULES | GND | SW4 | SW3 | SW2 | SW1 | GND | http://www.crystalfontz.com
Document: GRID: 0.5mm | VIA SIZE: 0.3mm | TRACE: 0.1524mm (6 mil) | REF TEXT: 1.27mm 8%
